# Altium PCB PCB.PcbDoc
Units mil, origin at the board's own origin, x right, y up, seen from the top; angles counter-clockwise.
Board outline 1710 x 3450 mil, 4 copper layers (Top Layer, GND, VCC, Bottom Layer), stack 61.2 mil thick; 25 components, 31 nets, 134 pads, 19 vias.
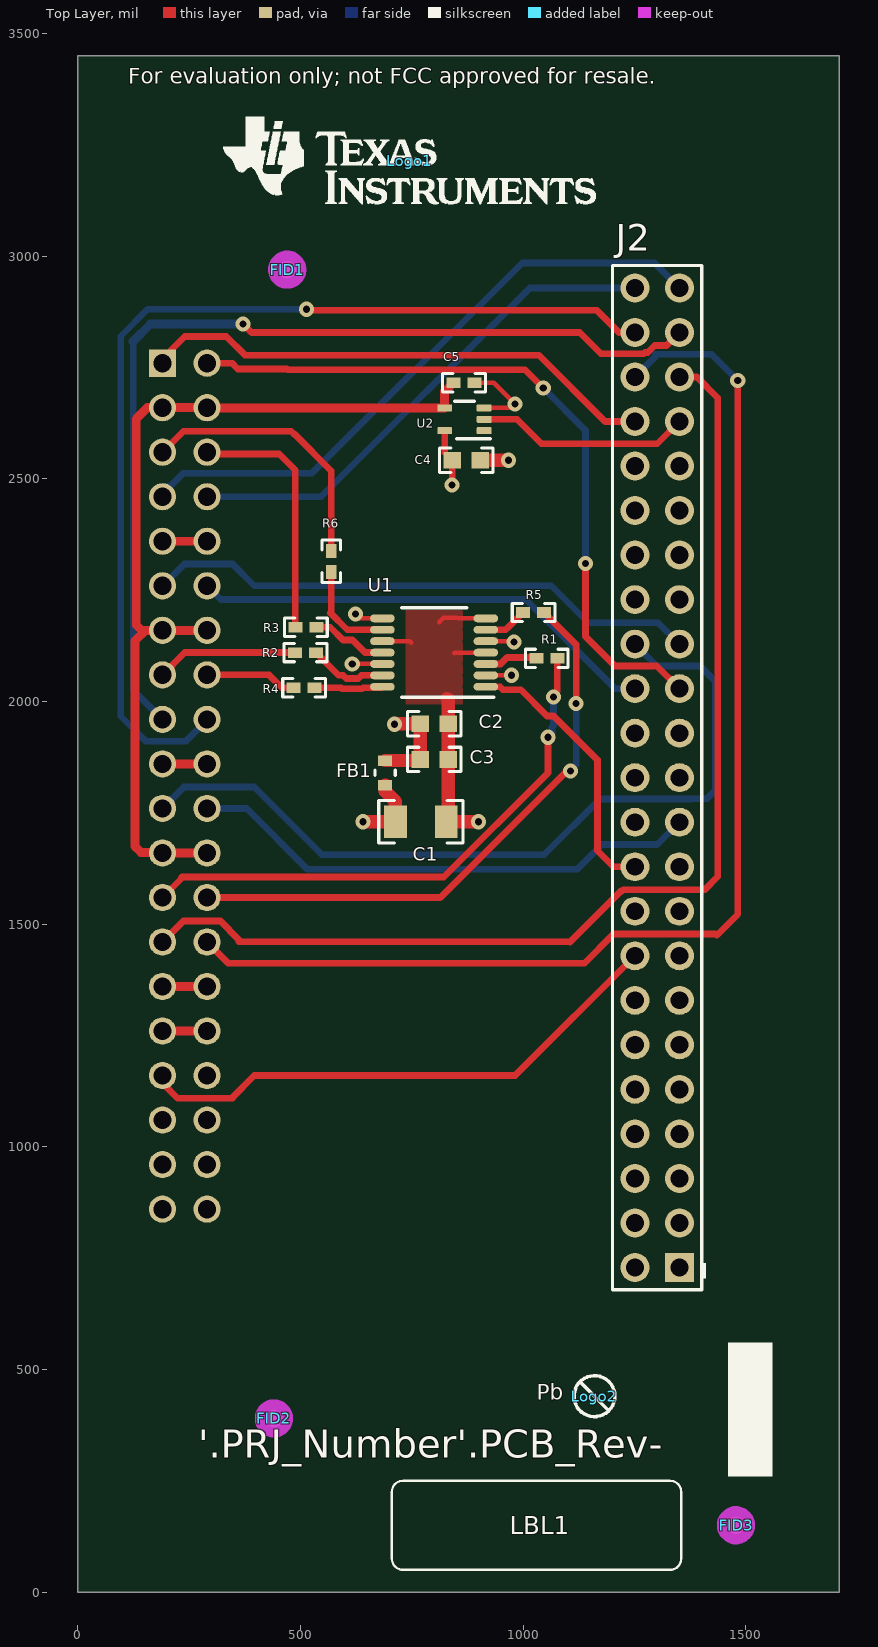
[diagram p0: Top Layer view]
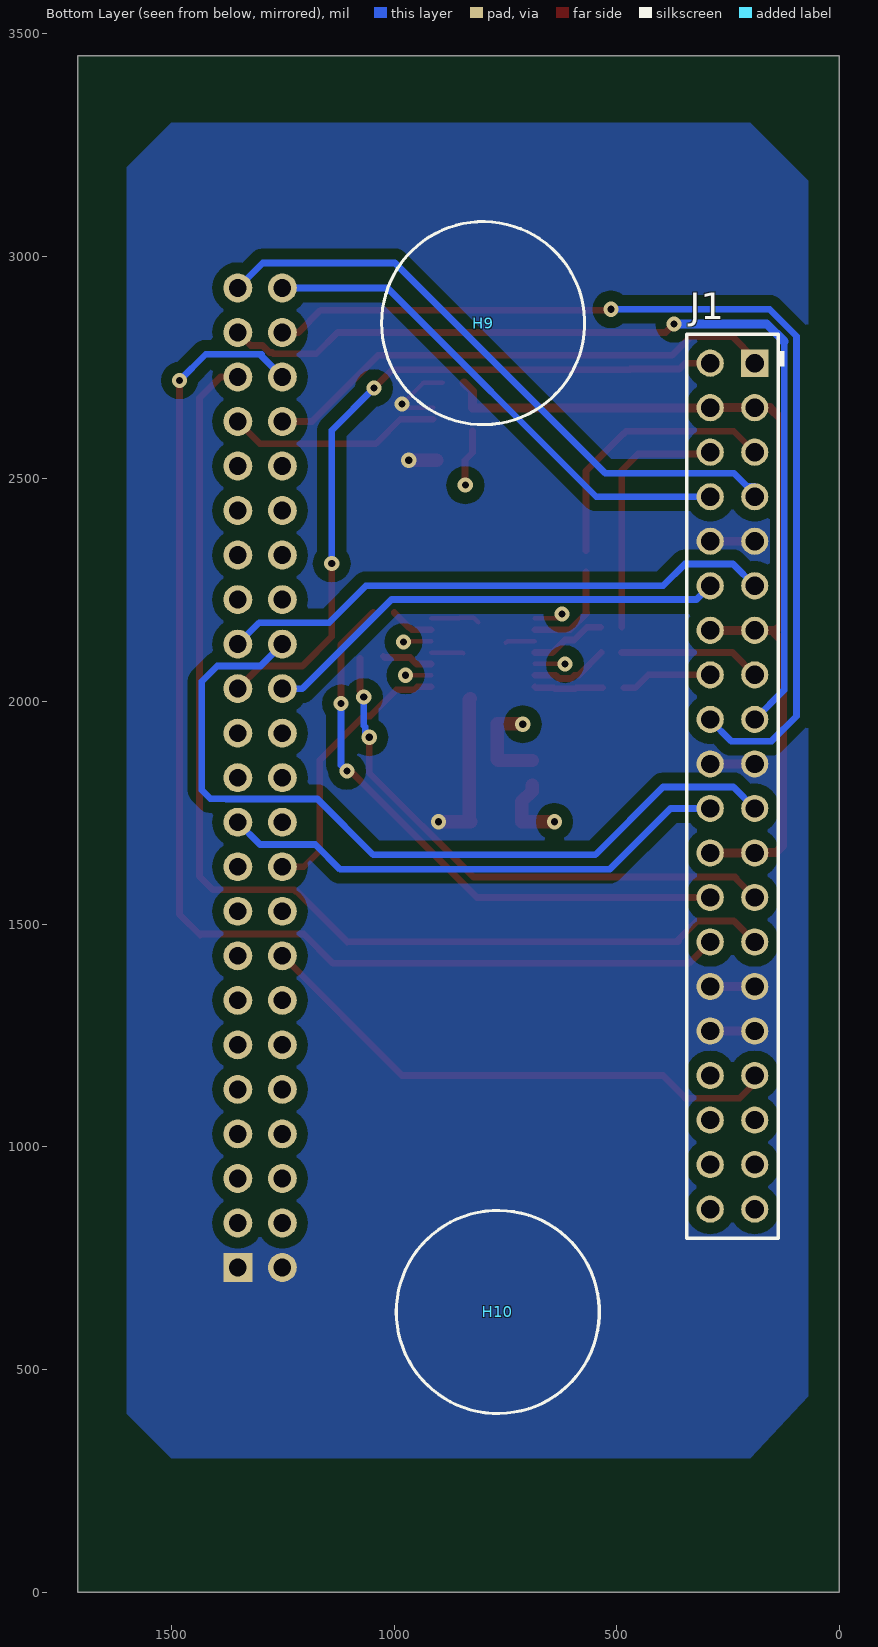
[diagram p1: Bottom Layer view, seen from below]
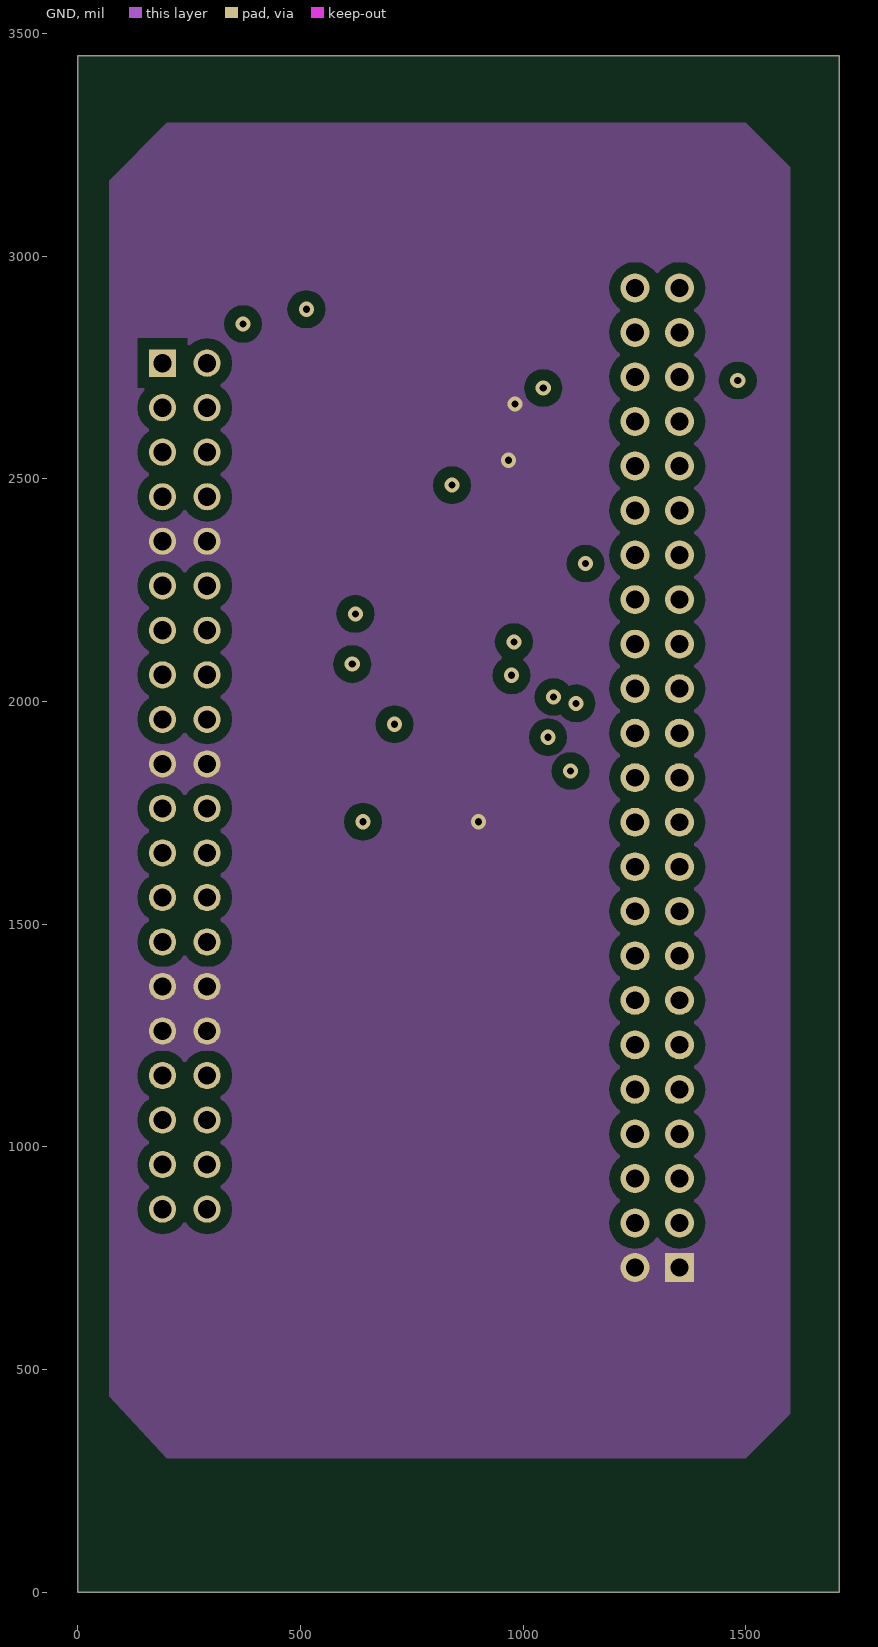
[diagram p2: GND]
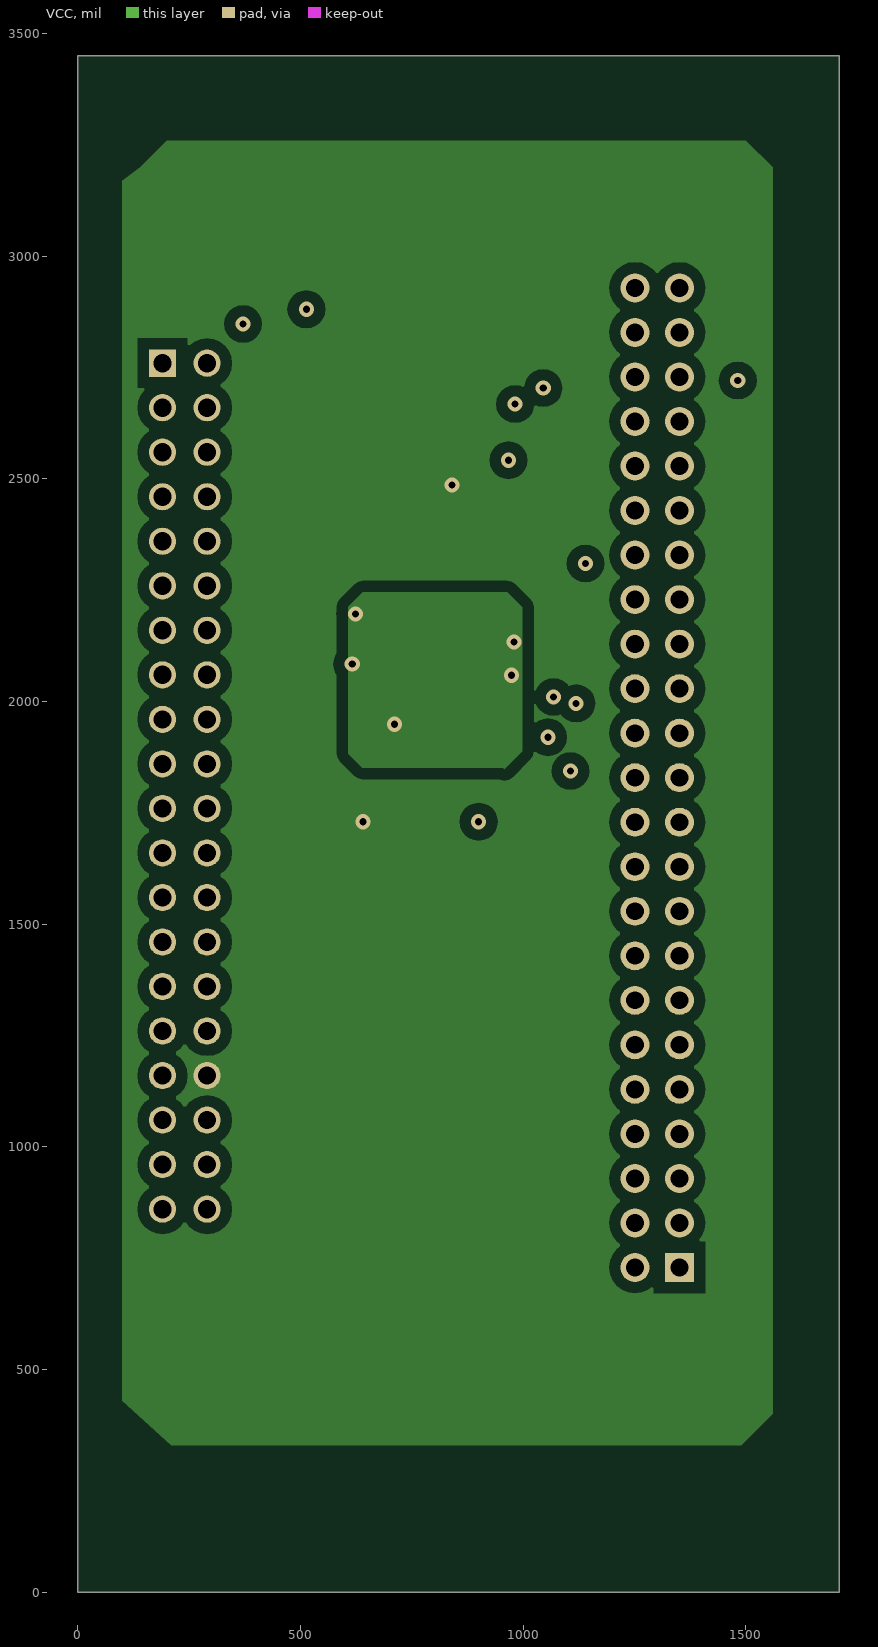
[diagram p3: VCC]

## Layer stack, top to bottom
Top Solder: solder mask 0.4, Solder Resist, Dk 3.5
Top Layer: signal copper 2.8
Dielectric1: core 16.6, FR-4, Dk 4.8
GND: signal copper 2.8
Dielectric 2: dielectric 16.8, FR-4, Dk 4.8
VCC: signal copper 2.8
Dielectric 3: dielectric 16.6, FR-4, Dk 4.8
Bottom Layer: signal copper 2.8
Bottom Solder: solder mask 0.4, Solder Resist, Dk 3.5

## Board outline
0,0 1710,0 1710,3450 0,3450 0,0

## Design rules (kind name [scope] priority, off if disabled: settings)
AcuteAngle [All] p1: minimum=4.50000000000000E+0001 checktracksonly=FALSE
AssemblyTestPointUsage [All] p1: valid=2
BoardOutlineClearance BoardOutlineClearance_MountingHoles [OnCopper and InComponentClass('Mounting Holes')] p1: gap=40
BoardOutlineClearance BoardOutlineClearance_Poly [OnCopper and IsPoly] p2: gap=25
BoardOutlineClearance [OnCopper and Not InComponentClass('Logo') and not InComponentClass('FiducialMark') and not InRegion(1000,500,4000,800) and not InPoly] p3: gap=75
Clearance Clearance_Keepouts [((IsTrack Or IsArc) And Not InPoly) And IsFree and IsKeepOut vs ((IsTrack Or IsArc) And Not InPoly) And IsFree and IsKeepOut] p1: gap=0
Clearance Clearance_Poly [InPolygon] p2: gap=25
Clearance [All] p3: gap=7.87
ComponentClearance ComponentClearance_MountingHoles_FiducialMarks [InComponentClass('Mounting Holes') vs InComponentClass('FiducialMark')] p1: gap=50 collisioncheckmode=3 verticalgap=10 showdistances=FALSE
ComponentClearance ComponentClearance_Shunt [InComponentClass('Header') vs InComponentClass('Shunt')] p2: gap=0 collisioncheckmode=3 verticalgap=0 showdistances=FALSE
ComponentClearance ComponentClearance_Logo [InComponentClass('Logo')] p3: gap=50 collisioncheckmode=3 verticalgap=10 showdistances=FALSE
ComponentClearance ComponentClearance_ScrewToNut [(HasFootprint('NY PMS 440 0025 PH')) vs (HasFootprint('Keystone_1902C'))] p4: gap=5 collisioncheckmode=3 verticalgap=10 showdistances=FALSE
ComponentClearance ComponentClearance_MountingHoles [InComponentClass('Mounting Holes')] p5: gap=250 collisioncheckmode=3 verticalgap=100000 showdistances=FALSE
ComponentClearance ComponentClearance_SmallPassives [HasFootprint('0201*') or HasFootprint('0402*') or HasFootprint('0508') or HasFootprint('0603*') or HasFootprint('0612') or HasFootprint('0805*') or HasFootprint('0815*') or HasFootprint('0830*') or HasFootprint('1206*') or HasFootprint('1210*') or HasFootprint('1808*') or HasFootprint('1812*') or HasFootprint('1825*') or HasFootprint('2010*') or HasFootprint('2220*') or HasFootprint('2225*') or HasFootprint('2512*') or HasFootprint('2728*') or HasFootprint('3518*') vs HasFootprint('0201*') or HasFootprint('0402*') or HasFootprint('0508') or HasFootprint('0603*') or HasFootprint('0612') or HasFootprint('0805*') or HasFootprint('0815*') or HasFootprint('0830*') or HasFootprint('1206*') or HasFootprint('1210*') or HasFootprint('1808*') or HasFootprint('1812*') or HasFootprint('1825*') or HasFootprint('2010*') or HasFootprint('2220*') or HasFootprint('2225*') or HasFootprint('2512*') or HasFootprint('2728*') or HasFootprint('3518*')] p6: gap=14.96 collisioncheckmode=3 verticalgap=10 showdistances=FALSE
ComponentClearance ComponentClearance_THtoSMT [IsThruComponent vs IsSMTComponent] p7: gap=40 collisioncheckmode=3 verticalgap=30 showdistances=FALSE
ComponentClearance ComponentClearance_THtoTH [IsThruComponent vs IsThruComponent] p8: gap=30 collisioncheckmode=3 verticalgap=30 showdistances=FALSE
ComponentClearance [All] p9: gap=30 collisioncheckmode=3 verticalgap=10 showdistances=FALSE
DiffPairsRouting [All] p1: maxlimit=100 minlimit=10 mostfreqgap=10 toplayer_minwidth=15 toplayer_maxwidth=15 toplayer_prefwidth=15 midlayer1_minwidth=15 midlayer1_maxwidth=15 midlayer1_prefwidth=15 midlayer2_minwidth=15 midlayer2_maxwidth=15 midlayer2_prefwidth=15 bottomlayer_minwidth=15 bottomlayer_maxwidth=15 bottomlayer_prefwidth=15 maxuncoupledlength=1000
FabricationTestPointUsage TestPointUsage [All] p1: valid=2 allowmultiple=FALSE
FabricationTestpoint Testpoint [All] p1: side=3 testpointundercomponent=TRUE minsize=40 maxsize=100 preferedsize=60 minholesize=0 maxholesize=40 preferedholesize=32 testpointgrid=1 allowsidetop=TRUE allowsidebottom=TRUE usegrid=TRUE gridtolerance=0.01
FanoutControl Fanout_LCC [IsLCC] p1: bgadir=Out bgaviamode=Centered fanoutstyle=Auto fanoutdirection=Alternating viagrid=1 // Fanout_LCC (Default Rule)
FanoutControl Fanout_BGA [IsBGA] p2: bgadir=Out bgaviamode=Centered fanoutstyle=Auto fanoutdirection=Alternating viagrid=1 // Fanout_BGA (Default Rule)
FanoutControl Fanout_Default [All] p4: bgadir=Out bgaviamode=Centered fanoutstyle=Auto fanoutdirection=Alternating viagrid=1 // Fanout_Default (Default Rule)
FanoutControl Fanout_Small [(CompPinCount < 5)] p5: bgadir=Out bgaviamode=Centered fanoutstyle=Auto fanoutdirection=OutThenIn viagrid=1 // Fanout_Small (Default Rule)
HoleSize [All] p1: absolutevalues=TRUE maxlimit=251 minlimit=7.87 maxpercent=80.000 minpercent=20.000
MinimumAnnularRing MinimumAnnularRing_ThermalPadVias [IsVia and InAnyComponent] p1: minimumring=5.91
MinimumAnnularRing [All] p2: minimumring=8
MinimumSolderMaskSliver MinimumSolderMaskSliver_Logo [InComponentClass('Logo') vs InComponentClass('Logo')] p1: minsoldermaskwidth=0.7
MinimumSolderMaskSliver [All] p2: minsoldermaskwidth=3.94
PlaneConnect [All] p1: planeconnectstyle=Relief reliefexpansion=10 reliefentries=4 reliefconductorwidth=10 reliefairgap=10
PolygonConnect [All] p1: connectstyle=Direct reliefconductorwidth=10 reliefentries=4 polygonreliefangle="90 Angle" airgapwidth=10
RoutingVias ThermalPadVias [IsVia and InAnyComponent] p1: holewidth=7.87 width=19.68 viastyle="Through Hole" minholewidth=7.87 minwidth=19.68 maxholewidth=12.99 maxwidth=23.62
RoutingVias [All] p2: holewidth=16 width=34 viastyle="Through Hole" minholewidth=7.87 minwidth=26 maxholewidth=40 maxwidth=65
SilkToBoardRegionClearance [Not ((IsComment or IsDesignator) And (Hide <> 'False')) and not InRegion(1000,500,4000,800)] p1:
SilkToSilkClearance SilkToSilkClearance_Pb-FreeLogo [(HasFootprint('Pb-Free_Overlay_Medium') OR HasFootprint('Pb-Free_Overlay_Small')) vs (HasFootprint('Pb-Free_Overlay_Medium') OR HasFootprint('Pb-Free_Overlay_Small'))] p1: silktosilkclearance=0
SilkToSilkClearance [All] p2: silktosilkclearance=4
SilkToSolderMaskClearance SilkToComponentPadClearance [(IsPad or IsFill or IsRegion) and InAnycomponent] p1: minsilkscreentomaskgap=5 clearancetoexposedcopper=TRUE
SilkToSolderMaskClearance "Silk to Solder Mask Opening" [All] p2: minsilkscreentomaskgap=4 clearancetoexposedcopper=FALSE
SolderMaskExpansion [All] p1: expansion=1.97
Width [All] p1: maxlimit=100 minlimit=6 preferedwidth=10 checkconnectedcopper=TRUE
15 further rules are at their usual default settings.

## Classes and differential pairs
component class Sheet1: C1 C2 C3 C4 C5 FB1 J1 R1 R2 R3 R4 R5 R6 U1 U2
component class Logo: Logo1
component class EVM_Hardware: FID1 FID2 FID3 H9 H10 LBL1 Logo1 Logo2 Logo3
component class FiducialMark: FID1 FID2 FID3
component class Label: LBL1

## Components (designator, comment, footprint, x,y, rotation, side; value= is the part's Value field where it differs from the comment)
C1 "885012208069" 1206 770,1730 r0 top
C2 "06033C104JAT2A" 0603 800,1950 r0 top
C3 "CGA3E3X5R1H105K080AB" 0603 800,1870 r0 top
C4 "GRM188R71C104KA01D" 0603 872,2542 r0 top
C5 "GRM1555C1E470JA01D" 0402 867,2716 r0 top
FB1 "MMZ1608B102CTA00" MMZ1608_095 690,1840 r270 top
FID1 "Fiducial" Fiducial10-20 470,2970 r0 top
FID2 "Fiducial" Fiducial10-20 440,390 r0 top
FID3 "Fiducial" Fiducial10-20 1478,150 r0 top
H9 "SJ-5303 (CLEAR)" Bumpon_SJ5003Transparent 800,2850 r180 bottom
H10 "SJ-5303 (CLEAR)" Bumpon_SJ5003Transparent 767,629 r180 bottom
J1 "SSW-120-01-T-D" Samtec_SSW-120-01-x-D 239.99,1810 r270 bottom
J2 "PBC23DFAN" Sullins_PBC23DFAN 1301,1829 r180 top
LBL1 "Size: 0.65\" x 0.20 \"" Label_650x200 1030,150 r0 top
Logo1 "Texas Instruments" TI_Stacked_Overlay_Small 745,3215 r0 top
Logo2 "Pb-Free Symbol" Pb-Free_Overlay_Small 1160,440 r0 top
Logo3 "FCC disclaimer" FCC_disclaimer 2350,3380 r0 top
R1 "CRCW04020000Z0ED" 0402 1053,2097 r180 top
R2 "CRCW04020000Z0ED" 0402 508,2031 r0 top
R3 "CRCW04020000Z0ED" 0402 512,2167 r0 top
R4 "CRCW04020000Z0ED" 0402 511,2110 r0 top
R5 "CRCW04020000Z0ED" 0402 1023.49,2200.01 r180 top
R6 "CRCW04020000Z0ED" 0402 569,2315 r270 top
U1 "CDCLVC1106PWR" PW0014A_N 800,2110 r180 top
U2 "SN74LVC1G17DCKR" DCK0005A_N 868,2634 r180 top

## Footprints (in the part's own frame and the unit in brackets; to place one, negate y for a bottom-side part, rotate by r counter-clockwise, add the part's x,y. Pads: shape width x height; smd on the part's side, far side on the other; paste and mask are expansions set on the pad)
0402 [mm] "0402 from SM-752 data"
  rect 0.8x0.6 smd: 1(-0.6,0) 2(0.6,0)
  silkscreen extent -1.22,-0.52 1.22,0.52, body extent -0.55,-0.3 0.55,0.3, height 0.6
0603 [mm] "0603 from SM-752 data"
  rect 1x0.95 smd: 1(-0.8,0) 2(0.8,0)
  silkscreen extent -1.52,-0.69 1.52,0.69, body extent -0.87,-0.47 0.87,0.47, height 1
1206 [mm] "1206 from SM-752 data"
  rect 1.3x1.85 smd: 1(-1.45,0) 2(1.45,0)
  silkscreen extent -2.4,-1.21 2.4,1.21, body extent -1.7,-0.9 1.7,0.9, height 1.35
Bumpon_SJ5003Transparent [mil] "3M Hemispherical Bumpon transparent"
  round 1 on Mech4: 0(0,0)
  silkscreen extent -228,-228 228,228, body extent -219,-219 219,219, height 197
DCK0005A_N [mm] "SOT353, 5-Leads, Body 2x1.3mm, Pitch 0.65mm, Lead Span 2.1mm, IPC Medium Density"
  rrect25% 0.85x0.4 smd: 1(-1.125,0.65) 2(-1.125,0) 3(-1.125,-0.65) 4(1.125,-0.65) 5(1.125,0.65)
  silkscreen extent -1.48,-1.02 0.55,1.1, body extent -1.14,-1 1.14,1, height 0.95
FCC_disclaimer [mil]
Fiducial10-20 [mm]
  round 1 smd mask+0.5: 1(0,0)
  Top Layer keep-out circle w1.178: c0,0 r0.5
Label_650x200 [mil] "Thermal Transfer Label"
  silkscreen extent -325,-100 325,100, body extent -325,-100 325,100, height 1
MMZ1608_095 [mm] "TDK"
  rect 0.6x0.8 smd: 1(-0.7,0) 2(0.7,0)
  silkscreen extent -0.15,-0.58 0.15,0.58, body extent -0.87,-0.47 0.87,0.47, height 0.95
Pb-Free_Overlay_Small [mil]
  silkscreen extent -46,-46 46,46
PW0014A_N [mm] "TSOP, 14-Leads, Body 5x4.4mm, Pitch 0.65mm, IPC Medium Density"
  oval 1.4x0.45 smd: 1(-2.95,1.95) 2(-2.95,1.3) 3(-2.95,0.65) 4(-2.95,0) 5(-2.95,-0.65) 6(-2.95,-1.3) 7(-2.95,-1.95) 8(2.95,-1.95) 9(2.95,-1.3) 10(2.95,-0.65) 11(2.95,0) 12(2.95,0.65) 13(2.95,1.3) 14(2.95,1.95)
  silkscreen extent -3.4,-2.55 1.85,2.55, body extent -3.21,-2.5 3.21,2.5, height 1
Samtec_SSW-120-01-x-D [mm] "Receptacle, 2.54mm, 2x20, TH"
  rect 1.55x1.55 hole 1.04: 1(-24.13,1.27)
  round 1.55 hole 1.04: 2(-24.13,-1.27) 3(-21.59,1.27) 4(-21.59,-1.27) 5(-19.05,1.27) 6(-19.05,-1.27) 7(-16.51,1.27) 8(-16.51,-1.27) 9(-13.97,1.27) 10(-13.97,-1.27) 11(-11.43,1.27) 12(-11.43,-1.27) 13(-8.89,1.27) 14(-8.89,-1.27) 15(-6.35,1.27) 16(-6.35,-1.27) 17(-3.81,1.27) 18(-3.81,-1.27) 19(-1.27,1.27) 20(-1.27,-1.27) 21(1.27,1.27) 22(1.27,-1.27) 23(3.81,1.27) 24(3.81,-1.27) 25(6.35,1.27) 26(6.35,-1.27) 27(8.89,1.27) 28(8.89,-1.27) 29(11.43,1.27) 30(11.43,-1.27) 31(13.97,1.27) 32(13.97,-1.27) 33(16.51,1.27) 34(16.51,-1.27) 35(19.05,1.27) 36(19.05,-1.27) 37(21.59,1.27) 38(21.59,-1.27) 39(24.13,1.27) 40(24.13,-1.27)
  silkscreen extent -25.78,-2.6 25.78,2.97, body extent -25.65,-2.48 25.65,2.48, height 8.41
Sullins_PBC23DFAN [mm] "Header, 100mil, 23x2, TH"
  rect 1.65x1.65 hole 1.016: 1(-1.27,27.94)
  round 1.65 hole 1.016: 2(1.27,27.94) 3(-1.27,25.4) 4(1.27,25.4) 5(-1.27,22.86) 6(1.27,22.86) 7(-1.27,20.32) 8(1.27,20.32) 9(-1.27,17.78) 10(1.27,17.78) 11(-1.27,15.24) 12(1.27,15.24) 13(-1.27,12.7) 14(1.27,12.7) 15(-1.27,10.16) 16(1.27,10.16) 17(-1.27,7.62) 18(1.27,7.62) 19(-1.27,5.08) 20(1.27,5.08) 21(-1.27,2.54) 22(1.27,2.54) 23(-1.27,0) 24(1.27,0) 25(-1.27,-2.54) 26(1.27,-2.54) 27(-1.27,-5.08) 28(1.27,-5.08) 29(-1.27,-7.62) 30(1.27,-7.62) 31(-1.27,-10.16) 32(1.27,-10.16) 33(-1.27,-12.7) 34(1.27,-12.7) 35(-1.27,-15.24) 36(1.27,-15.24) 37(-1.27,-17.78) 38(1.27,-17.78) 39(-1.27,-20.32) 40(1.27,-20.32) 41(-1.27,-22.86) 42(1.27,-22.86) 43(-1.27,-25.4) 44(1.27,-25.4) 45(-1.27,-27.94) 46(1.27,-27.94)
  silkscreen extent -2.79,-29.21 2.54,29.21, body extent -2.54,-29.21 2.54,29.21, height 10.62
TI_Stacked_Overlay_Small [mil]
  silkscreen extent -418,-98 418,98

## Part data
C1: library part GRM31CR71E106KA12L, "CAP, CERM, 10uF, 25V, +/-10%, X7R, 1206"
C2: "CAP, CERM, 0.1uF, 25V, +/-5%, X7R, 0603"
C3: library part GRM188R61H105KAALD, "CAP, CERM, 1uF, 50V, +/-10%, X5R, 0603"
C4: "CAP, CERM, 0.1 µF, 16 V, +/- 10%, X7R, 0603"
C5: "CAP, CERM, 47 pF, 25 V,+/- 5%, C0G/NP0, 0402"
FB1: "Ferrite Bead, 1000 ohm @ 100 MHz, 0.3 A, 0603"
FID1 FID2 FID3: "Fiducial mark.  There is nothing to buy or mount."
H9 H10: "Bumpon, Hemisphere, 0.44 X 0.20, Clear"
J1: "Receptacle, 2.54mm, 2x20, TH"
J2: "Header, 100 mil, 23x2, Gold, TH"
LBL1: library part THT-14-423-10, "Thermal Transfer Printable Labels, 0.650\" W x 0.200\" H - 10,000 per roll"
Logo1: library part TI_Logo, "Texas Instrument Corporate Signature"
Logo2: library part Pb-Free
Logo3: library part FCC_disclaimer, "FCC_disclaimer"
R1 R2 R3 R4 R5 R6: "RES, 0, 5%, 0.063 W, 0402"
U1: "Low Jitter, 1:6 LVCMOS Fan-out Clock Buffer, PW0014A (TSSOP-14)"
U2: "SINGLE SCHMITT-TRIGGER BUFFER, DCK0005A (SOT-SC70-5)"

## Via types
v1: diameter 34, hole 16, Top Layer to Bottom Layer, 19 vias

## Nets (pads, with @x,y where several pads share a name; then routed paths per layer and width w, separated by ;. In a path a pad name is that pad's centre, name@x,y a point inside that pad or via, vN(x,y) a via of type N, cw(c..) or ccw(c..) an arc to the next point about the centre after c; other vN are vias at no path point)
+3.3V: C1.1 C4.1 FB1.2 J1.34 U2.5 | length 294.4
  Top Layer w15: U2.5 823.71,2558.8 C4.1 840.5,2490.5 840,2490 v1(840,2486)
  Top Layer w30: v1(640,1730) C1.1 712.91,1775.67 690,1798.58 FB1.2
CS1: C5.1 J1.3 J1.4 J1.13 J1.14 J1.23 J1.24 U2.4 | length 2054.7
  Top Layer w20: J1.24 J1.23 189,1661 142,1661 128,1675 128,2136 145,2153 145,2158 ; J1.14 J1.13 147,2160 145,2158 ; C5.1 823.71,2696.33 U2.4 290.41,2659.59 J1.4 J1.3 156,2660 131,2635 131,2172 145,2158
CS1TO6: J2.39 U2.2 | length 482.2
  Top Layer w15: U2.2 986,2634 1041,2579 1301,2579 J2.39
DGND: C1.2 C2.2 C3.2 C4.2 C5.2 J1.9 J1.10 J1.19 J1.20 J1.29 J1.30 J1.31 J1.32 J2.1 J2.2 U1.4 U1.7 U1.10 U2.3 | length 1248.7
  Top Layer w10: U1.10 745.41,2135.59 749,2132 ; 811,2178 821,2188 852,2188 853.23,2186.77 U1.7 ; 845,2109 846,2110 U1.4 ; C5.2 934,2716 v1(982,2668) 973.59,2659.59 U2.3
  Top Layer w20: J1.31 J1.32 ; J1.29 J1.30 ; J1.19 J1.20 ; J1.9 J1.10
  Top Layer w30: 829,2007 831.5,2004.5 C2.2 C3.2 831.5,1734.41 C1.2 v1(900,1730) ; C4.2 v1(967,2542)
NetC2_1: C2.1 C3.1 FB1.1 U1.2 U1.5 U1.8 U1.12 | length 473.8
  Top Layer w10: v1(616,2084) 616.41,2084.41 U1.12 ; v1(623,2197) 623,2191.54 627.77,2186.77 U1.8 ; U1.2 967.82,2058.82 968,2059 v1(974,2059) ; U1.5 977.41,2135.59 v1(979,2134)
  Top Layer w30: FB1.1 766.06,1867.56 C3.1 C2.1 v1@712,1950
  other v1: 711,1949
NetR1_2: R1.2 U1.3 | length 115.1
  Top Layer w15: U1.3 949.41,2084.41 964,2099 1021.1,2099 R1.2@1024.02,2101.93
NetR2_2: R2.2 U1.14 | length 155
  Top Layer w15: R2.2 590.87,2031 593.12,2028.75 638.88,2028.75 641.13,2031 681.63,2031 U1.14
NetR3_2: R3.2 U1.11 | length 171.8
  Top Layer w15: R3.2 566.65,2167 595.34,2138.31 616.24,2138.31 644.55,2110 U1.11
NetR4_2: R4.2 U1.13 | length 176.4
  Top Layer w15: R4.2 585.8,2058.82 595.4,2058.82 602.59,2051.63 629.41,2051.63 636.6,2058.82 U1.13
NetR5_2: R5.2 U1.6 | length 99.8
  Top Layer w15: U1.6 960.4,2161.18 965.59,2166.37 966.23,2166.37 R5.2
NetR6_2: R6.2 U1.9 | length 225.7
  Top Layer w15: R6.2 569,2201 567,2199 604.82,2161.18 U1.9
OE: J1.33 J2.16 | length 1225.8
  Top Layer w15: J1.33 189.99,1143.01 224,1109 347,1109 347,1111 396,1160 982,1160 J2.16
SCLK_1: J1.5 R6.1 | length 614.7
  Top Layer w15: J1.5 237,2607 479,2607 485,2601 486,2601 569,2518 R6.1
SCLK_2: J1.6 R3.1 | length 567.7
  Top Layer w15: J1.6 294,2556 452,2556 488.38,2519.62 R3.1
SCLK_3: J1.15 R4.1 | length 320.1
  Top Layer w15: J1.15 240,2110 R4.1@489.37,2110
SCLK_4: J1.16 R2.1 | length 206.4
  Top Layer w15: J1.16 429,2060 458,2031 R2.1
SCLK_5: J1.25 R1.1 | length 1243.6
  Top Layer w15: J1.25 232,1602 232,1604 233.89,1605.89 821.67,1605.89 1055.69,1839.9 v1(1055.69,1919.82) ; v1@1068,2015 1076.62,2023.62 R1.1
  Bottom Layer w15: v1(1055.69,1919.82) 1064.81,1928.94 1064.81,1943.08 1068,1946.26 v1(1068,2010)
SCLK_6: J1.26 R5.1 | length 1331.3
  Top Layer w15: J1.26 814,1560 1098,1844 v1(1106,1844) ; R5.1 1119,2128.12 v1(1119,1996)
  Bottom Layer w15: v1@1099.51,1844 v1(1106,1844) 1119,1857 v1(1119,1996)
SCLK_16: J2.20 U1.1 | length 621.9
  Top Layer w15: U1.1 947.99,2033.23 954.59,2026.63 994.66,2026.63 1053.65,1967.64 1068,1967.64 1166.64,1869 1167,1869 1167,1664.78 1202.78,1629 J2.20
SDI_1: J1.1 J2.40 | length 1170.8
  Top Layer w15: J1.1 189.99,2770 239.99,2820 333,2820 375,2778 1035,2778 1184,2629 J2.40
SDI_2: J1.2 J2.27 | length 1635
  Top Layer w15: J1.2 346,2760 359,2747 469.51,2747 471,2745.51 1003.49,2745.51 v1(1045,2704) ; v1(1140,2310) 1140,2146 1206,2080 1300,2080 J2.27
  Bottom Layer w15: v1(1045,2704) 1140,2609 v1(1140,2310)
SDI_3: J1.11 J2.29 | length 1255.9
  Bottom Layer w15: J1.11 238.99,2309 347,2309 396,2260 1063,2260 1146,2177 1303,2177 J2.29
SDI_4: J1.12 J2.28 | length 1056.7
  Bottom Layer w15: J1.12 320.61,2229.37 1005.63,2229.37 1206,2029 J2.28
SDI_5: J1.21 J2.30 | length 1844.7
  Bottom Layer w15: J1.21 237.99,1808 396,1808 548,1656 1047,1656 1172.15,1781.15 1376.82,1781.15 1377.68,1782 1413,1782 1432,1801 1432,2045 1397,2080 1300,2080 J2.30
SDI_6: J1.22 J2.21 | length 1161.5
  Bottom Layer w15: J1.22 379,1760 515.78,1623.22 1121.22,1623.22 1177,1679 1301,1679 J2.21
SDO_1: J1.7 J2.45 | length 1394
  Bottom Layer w15: J1.7@190,2482.87 202.47,2482.87 204.67,2480.67 237,2513 526,2513 998,2985 1295,2985 J2.45
SDO_2: J1.8 J2.46 | length 1155.3
  Bottom Layer w15: J1.8 546,2460 1015,2929 J2.46
SDO_3: J1.17 J2.43 | length 2167
  Top Layer w15: v1(371,2848) 390,2829 1127,2829 1174.85,2781.15 1270.82,2781.15 1273.68,2784 1279.65,2784 1295.53,2799.87 1321.87,2799.87 J2.43
  Bottom Layer w15: 124,2809 124,2025.99 J1.17
  Bottom Layer w20: 124,2809 163,2848 v1(371,2848)
SDO_4: J1.18 J2.44 | length 2293.6
  Top Layer w15: v1(513,2881) 515,2879 1165,2879 1215,2829 J2.44
  Bottom Layer w15: J1.18 289.99,1957.99 243,1911 152,1911 96.13,1966.87 96.13,2820.55 156.58,2881 v1(513,2881)
SDO_5: J1.27 J2.41 | length 2529.8
  Top Layer w15: J1.27 236.95,1506.96 319.97,1506.96 361,1465.93 361,1461 1105,1460 1219.49,1574.49 1221.86,1574.49 1224.37,1577 1407,1577 1437,1607 1437,2682 1390,2729 J2.41
SDO_6: J1.28 J2.42 | length 2738.4
  Top Layer w15: J1.28 337.98,1412 1137,1412 1203,1478 1432,1478 1435,1475 1482,1522 v1(1482,2721)
  Bottom Layer w15: J2.42 1297,2775 1297,2780 1423,2780 v1(1482,2721)
pads on no net: FID1.1 FID2.1 FID3.1 H9.0 H10.0 J1.35 J1.36 J1.37 J1.38 J1.39 J1.40 J2.3 J2.4 J2.5 J2.6 J2.7 J2.8 J2.9 J2.10 J2.11 J2.12 J2.13 J2.14 J2.15 J2.17 J2.18 J2.19 J2.22 J2.23 J2.24 J2.25 J2.26 J2.31 J2.32 J2.33 J2.34 J2.35 J2.36 J2.37 J2.38 U2.1

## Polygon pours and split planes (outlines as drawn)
DGND on GND "GND_DGND_P001" (solid, pour order 1): 70,3170 200,3300 1500,3300 1600,3200 1600,400 1500,300 200,300 70,440
+3.3V on VCC "VCC-No Net" (solid, pour order 2): 100,560 100,1860 100,2545.51 100,3170 140,3200 200,3260 1500,3260 1560,3200 1560,400 1490,330 210,330 100,430 100,470 100,500
NetC2_1 on VCC "Top Layer-No Net" (solid, pour order 0): 607,2213 640,2246 964,2246 997,2213 998,2212 998,1889 998,1888 958,1848 955,1851 641,1851 639,1851 607,1883 607,2213
DGND on Bottom Layer "BOTTOM_LAYER_DGND_P003" (solid, pour order 3): 70,3170 200,3300 1500,3300 1600,3200 1600,400 1500,300 200,300 70,440
DGND on Top Layer "Top Layer-No Net 1" (solid, pour order 7): 736,2205 864,2206.46 864,2193.51 864,1994 736,1994

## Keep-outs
Keep-Out Layer:
  text ".Layer_Name" at 577,-858.49 h60

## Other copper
Top Layer:
  text ".Layer_Name" at 577,-858.49 h60
Bottom Layer:
  text ".Layer_Name" at 577,-858.49 h60

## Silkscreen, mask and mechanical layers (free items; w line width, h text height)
Top Overlay:
  region: 1560,260 1560,560 1460,560 1460,260
  text "'.PRJ_Number'.PCB_Rev-" at 270,280 h108.27
  text ".Layer_Name" at 577,-858.49 h60
Bottom Overlay:
  text ".Layer_Name" at 577,-858.49 h60
Top Paste:
  text ".Layer_Name" at 577,-858.49 h60
Bottom Paste:
  text ".Layer_Name" at 577,-858.49 h60
Top Solder:
  text ".Layer_Name" at 577,-858.49 h60
  text ".Layer_Name" at 577,-858.49 h60
Bottom Solder:
  text ".Layer_Name" at 577,-858.49 h60
Drill Guide:
  text ".Layer_Name" at 577,-858.49 h60
M1 Board Outline:
  the board outline again, w10
  text ".Layer_Name" at 577,-858.49 h60
M2 Board Dimensions:
  rectangle: 0,-275 125,-150
  rectangle: 125,-400 500,-275
  lines w7: 0,-275 1000,-275 ; 125,-400 125,-150 ; 250,-400 250,-150 ; 500,-400 500,-150 ; 750,-400 750,-150 ; 0,-400 1000,-400 1000,-150 0,-150 0,-400
  text ".Layer_Name" at 577,-858.49 h60
M3 3D STEP Top:
  text ".Layer_Name" at 577,-858.49 h60
M4 3D STEP Bottom:
  text ".Layer_Name" at 577,-858.49 h60
M5 Assembly Top:
  lines w10: -292,-930.17 6308,-930.17 ; -292,-726.83 6310,-726.83 ; -292,-523.5 -292,-1133.5 3713,-1133.5 6310,-1133.5 6310,-523.5 -291.5,-523.5 -291.5,-1133.5 1284,-1133.5 ; 2173,-1133.5 2173,-523.5 ; 3440,-726.83 3440,-523.5 ; 4280,-726.83 4280,-523.5 ; 4902,-1140 4902,-937.17
  text "COMPONENTS MARKED 'DNP' SHOULD NOT BE POPULATED." at 1153.5,-318.5 h60
  text "ASSEMBLY VARIANT:" at 1153,-434 h60
  text ".VariantName" at 2189,-434 h60
  text "PCB VIEWED FROM TOP SIDE" at -228.5,-655.67 h60
  text "BOARD #:" at 2248,-655.67 h60
  text ".PRJ_Number" at 2793.5,-655.67 h60
  text "REV:" at 3638,-655.67 h60
  text ".PCB_Rev" at 3929.5,-655.67 h60
  text "SVN REV:" at 4476,-655.67 h60
  text ".VersionControl_RevNumber" at 4982,-655.67 h60
  text "TID #:" at 2248,-859 h60
  text ".TID" at 2793.5,-859 h60
  text "PLOT NAME =" at -228.5,-1064.34 h60
  text ".plot_File_Name" at 577,-1064.34 h60
  text "GENERATED    :" at 2250,-1064.34 h60
  text ".Print_Date" at 3119.5,-1064.34 h60
  text ".Print_Time" at 3848.5,-1064.34 h60
  text "TEXAS INSTRUMENTS" at 5113,-1064.34 h60
M6 Assembly Bottom:
  lines w10: -292.5,-727.33 6309.5,-727.33 ; -290.5,-930.67 6309.5,-930.67 ; 1115.5,-1140.5 1115.5,-937.67 ; 1737.5,-727.33 1737.5,-524 ; 2577.5,-727.33 2577.5,-524 ; 3844.5,-1134 3844.5,-524 ; 4733.5,-1134 6309,-1134 6309,-524 -292.5,-524 -292.5,-1134 2304.5,-1134 6309.5,-1134 6309.5,-524
  text "COMPONENTS MARKED 'DNP' SHOULD NOT BE POPULATED." at 6102,-318 h60
  text ".VariantName" at 5058,-434 h60
  text "ASSEMBLY VARIANT:" at 6097,-434 h60
  text ".VersionControl_RevNumber" at 1035.5,-656.17 h60
  text "SVN REV:" at 1541.5,-656.17 h60
  text ".PCB_Rev" at 2088,-656.17 h60
  text "REV:" at 2379.5,-656.17 h60
  text ".PRJ_Number" at 3224,-656.17 h60
  text "BOARD #:" at 3769.5,-656.17 h60
  text "PCB VIEWED FROM BOTTOM SIDE" at 6246,-656.17 h60
  text ".TID" at 3224,-859.5 h60
  text "TID #:" at 3769.5,-859.5 h60
  text "TEXAS INSTRUMENTS" at 904.5,-1064.84 h60
  text ".Print_Time" at 2169,-1064.84 h60
  text ".Print_Date" at 2898,-1064.84 h60
  text "GENERATED    :" at 3767.5,-1064.84 h60
  text ".plot_File_Name" at 5440.5,-1064.84 h60
  text "PLOT NAME =" at 6246,-1064.84 h60
M9 Title Sheet:
  drawing of 57 lines, arcs and shapes, not listed
  text "1" at 739.84,8036.5 h70
  text "2" at 3235.5,8036.5 h70
  text "3" at 5724.84,8036.5 h70
  text "4" at 8231.51,8036.5 h70
  text "5" at 10730.5,8036.5 h70
  text "6" at 13235.5,8036.5 h70
  text "A" at -416.5,6893.5 h70
  text "A" at 14383.5,6893.5 h70
  text "B" at -416.5,4513.5 h70
  text "B" at 14383.5,4513.5 h70
  text "C" at -416.5,2138.5 h70
  text "C" at 14383.5,2138.5 h70
  text "PROJECT TITLE:" at 11343.5,277.5 h45
  text ".PRJ_Title" at 11393.5,144.17 h70
  text "DESIGNED FOR:" at 11343.5,-23.5 h45
  text ".PRJ_Customer" at 11393.5,-163.5 h70
  text "D" at -416.5,-231.5 h70
  text "D" at 14383.5,-231.5 h70
  text "FILE NAME:" at 11343.5,-323.5 h45
  text ".PCB_File_Name_No_Path" at 11393.5,-443.5 h70
  text "Texas Instruments (TI) and/or its licensors do not warrant the accuracy or completeness of this specification" at 6374,-605.34 h45
  text "ENGINEER:" at 11343.5,-613.5 h45
  text "LAYOUT BY:" at 12848.5,-613.5 h45
  text "or any information contained therein. TI and/or its licensors do not warrant that this design will meet" at 6329.01,-718 h45
  text ".PRJ_Engineer" at 11393.5,-768.49 h70
  text ".PCB_Layout" at 12899,-768.49 h70
  text "the specifications, will be suitable for your application or fit for any particular purpose, or will operate in" at 6329.01,-830.67 h45
  text ".Layer_Name" at 577,-858.49 h60
  text "ALTIUM DESIGNER VERSION:" at 12848.5,-923.5 h45
  text "an implementation. TI and/or its licensors do not warrant that the design is production worthy. You should" at 6329.01,-943.33 h45
  text "completely validate and test your design implementation to confirm the system functionality for your application." at 6374,-1056 h45
  text ".print_Scale" at 11393.5,-1056.83 h70
  text ".Application_BuildNumber" at 12899,-1056.83 h70
  text "1" at 739.84,-1263.5 h70
  text "2" at 3235.5,-1263.5 h70
  text "3" at 5724.84,-1263.5 h70
  text "4" at 8231.51,-1263.5 h70
  text "5" at 10730.5,-1263.5 h70
  text "6" at 13235.5,-1263.5 h70
M10 Fab Notes:
  drawing of 173 lines, arcs and shapes, not listed
  text "DESIGN INFORMATION" at 12378.02,6201 h60
  text "MIN. TRACK WIDTH:" at 11733.46,6021 h60
  text "8" at 12829.7,6021 h60
  text "MIL" at 12984.46,6021 h60
  text "MIN. CLEARANCE:" at 11733.46,5889 h60
  text "0.2" at 12769.7,5889 h60
  text "mm" at 12984.46,5889 h60
  text "MIN. VIA PAD SIZE:" at 11733.46,5757 h60
  text "24" at 12799.71,5757 h60
  text "MIL" at 12984.46,5757 h60
  text "0.05mm (2MIL)" at 12428.46,5615.29 h60
  text "MINIMUM ANNULAR RING" at 11404.23,5611 h60
  text "EXTERNAL" at 13136.46,5611 h60
  text "PER" at 11604.23,5493 h60
  text "IPC-D-275 CLASS 2 LEVEL C" at 11824.23,5493 h60
  text "MIL, HOLES" at 13312.46,5380.71 h60
  text "+/-" at 12920,5380 h60
  text "+/-" at 13774,5380 h60
  text "REGISTRATION TOLERANCES:" at 11404.23,5375 h60
  text "METAL" at 12604,5375 h60
  text "5" at 13180.2,5375 h60
  text "3" at 14013.2,5375 h60
  text "MIL" at 14129.46,5375 h60
  text "+/-" at 13774,5262 h60
  text "HOLE SIZE TOLERANCE (UNLESS OTHERWISE SPECIFIED):" at 11404.23,5257 h60
  text "3" at 14013.2,5257 h60
  text "MIL" at 14129.46,5257 h60
  text "MATERIAL:" at 11329.46,5047.54 h60
  text "FR-4 High Tg" at 12315.9,4907.21 h60
  text "FR-408" at 11750.46,4898.64 h60
  text "OTHER" at 13238.46,4898.64 h60
  text "X" at 12161,4895 h60
  text "62 MIL (1.6mm) +/-10%" at 12070.56,4735.92 h60
  text "THICKNESS:" at 11404.23,4731.64 h60
  text "X" at 11942.4,4731.64 h60
  text "OTHER" at 13355.46,4731.64 h60
  text "TOLERANCE:" at 11404.23,4573.64 h60
  text "X" at 12243.53,4573.64 h60
  text "ANSI IPC-6012 TYPE 3 CLASS 2" at 12430.48,4573.64 h60
  text "OTHER +/-" at 12430.46,4417.64 h60
  text "BOW & TWIST:" at 11404.23,4260.64 h60
  text "X" at 12243.53,4260.64 h60
  text "ANSI IPC-6012 TYPE 3 CLASS 2" at 12430.48,4260.64 h60
  text "OTHER +/-" at 12430.46,4102.13 h60
  text "DRILLING:" at 11329.46,3963.64 h60
  text "REFERENCE:" at 11404.23,3846.64 h60
  text "X" at 12052.46,3846.64 h60
  text "AS SHOWN" at 12239.46,3846.64 h60
  text "X" at 12953.46,3846.64 h60
  text "NC_DRILL FILES" at 13090.46,3846.64 h60
  text "PTH COPPER THICKNESS:" at 11404.23,3688.64 h60
  text "X" at 12534.46,3688.64 h60
  text "20-30 um" at 12671.46,3688.64 h60
  text "OTHER" at 13388.46,3688.64 h60
  text "BOARD FINISH:" at 11329.46,3529.64 h60
  text "SILKSCREEN:" at 11484.68,3411.64 h60
  text "X" at 12433.46,3411.64 h60
  text "TOP" at 12559.46,3411.64 h60
  text "X" at 12943.46,3411.64 h60
  text "BOTTOM" at 13070.46,3411.64 h60
  text "SILKSCREEN COLOR:" at 11484.68,3244.64 h60
  text "X" at 12432.42,3244.64 h60
  text "WHITE" at 12559.46,3244.64 h60
  text "OTHER" at 13070.46,3244.64 h60
  text "X" at 12563.42,3085.44 h60
  text "GREEN" at 12690.46,3085.44 h60
  text "OTHER" at 13308.46,3085.44 h60
  text "SOLDER RESIST COLOR:" at 11484.68,3074.64 h60
  text "X" at 12563.42,2915.44 h60
  text "MATTE" at 12690.46,2915.44 h60
  text "SEMI-GLOSS" at 13308,2914.8 h60
  text "IMMERSION GOLD (ENIG)" at 12390.46,2726.92 h60
  text "ENEPIG" at 13728,2723.64 h60
  text "SURFACE FINISH:" at 11329.46,2722.64 h60
  text "X" at 12203.51,2722.64 h60
  text "IMM. TIN/SILVER OR EQUIV" at 11659,2565.64 h60
  text "OTHER" at 13090.46,2565.64 h60
  text "ARRAY/PANEL:" at 11329.46,2386.64 h60
  text "CUT AND TRIM PER M1 BOARD OUTLINE" at 12390.46,2382.35 h60
  text "N.C. ROUTE" at 12390.46,2230.64 h60
  text "X" at 13069.46,2230.64 h60
  text "V. SCORE" at 13256.46,2230.64 h60
  text "CERTIFICATION:" at 11329.46,2093.64 h60
  text "MATERIALS AND WORKMANSHIP FOR ALL PCBS" at 12054.46,2093.64 h60
  text "TO MEET OR EXCEED THE REQUIREMENTS OF:" at 12054.46,1995.64 h60
  text "X" at 11680.96,1859.13 h60
  text "ANSI IPC-A-600F CLASS ->" at 11819.96,1859.13 h60
  text "X" at 13459.02,1859.13 h60
  text "2" at 13577.96,1859.14 h60
  text "1" at 13262.96,1857.64 h60
  text "3" at 13931.96,1857.64 h60
  text "X" at 12495.02,1699.64 h60
  text "RoHS" at 12631.96,1699.64 h60
  text "OTHER" at 13276.36,1699.64 h60
  text "PER ORDER" at 13673.42,1699.64 h60
  text "ALL BOARDS MUST MEET OR EXCEED UL94-V0 REQUIREMENTS." at 11357,1534 h60
  text "PCB MUST BEAR THE UL94V-0 UL REGISTERED MATERIAL ID NUMBER" at 11357,1414 h60
  text "ADDITIONAL REQUIREMENTS:" at 11329.46,1240.64 h60
  text "MICROSECTION:" at 11404.23,1125.64 h60
  text "YES" at 12309.96,1125.64 h60
  text "REQUIRED" at 13171.46,969.49 h60
  text "BARE BOARD ELEC. TEST:" at 11404.23,966.64 h60
  text "NONE" at 12709.96,966.64 h60
  text "X" at 13044.46,966.64 h60
  text "PER ORDER" at 13763.46,966.64 h60
  text ".Layer_Name" at 577,-858.49 h60
M11 Gerber Information:
  lines w10: -292,-930.17 6308,-930.17 ; -292,-726.83 6310,-726.83 ; -292,-523.5 -292,-1133.5 3713,-1133.5 6310,-1133.5 6310,-523.5 -291.5,-523.5 -291.5,-1133.5 1284,-1133.5 ; 2173,-1133.5 2173,-523.5 ; 3440,-726.83 3440,-523.5 ; 4280,-726.83 4280,-523.5 ; 4902,-1140 4902,-937.17
  text "ALL ARTWORK VIEWED FROM TOP SIDE" at -228.5,-655.67 h60
  text "BOARD #:" at 2248,-655.67 h60
  text ".PRJ_Number" at 2793.5,-655.67 h60
  text "REV:" at 3638,-655.67 h60
  text ".PCB_Rev" at 3929.5,-655.67 h60
  text "SVN REV:" at 4476,-655.67 h60
  text ".VersionControl_RevNumber" at 4982,-655.67 h60
  text "LAYER NAME =" at -228.5,-858.49 h60
  text "TID #:" at 2248,-859 h60
  text ".TID" at 2793.5,-859 h60
  text "PLOT NAME =" at -228.5,-1064.34 h60
  text ".plot_File_Name" at 577,-1064.34 h60
  text "GENERATED    :" at 2250,-1064.34 h60
  text ".Print_Date" at 3119.5,-1064.34 h60
  text ".Print_Time" at 3848.5,-1064.34 h60
  text "TEXAS INSTRUMENTS" at 5113,-1064.34 h60
M12 Stackup:
  drawing of 191 lines, arcs and shapes, not listed
  text "Layer" at 9790.34,7830 h60
  text "Name" at 10200.26,7830 h60
  text "Material" at 11130,7830 h60
  text "Thickness" at 11989.77,7830 h60
  text "Constant" at 12639.6,7830 h60
  text "Board Layer Stack" at 13209.46,7830 h60
  text "1" at 9790.34,7710 h60
  text "Top Overlay" at 10200.26,7710 h60
  text "2" at 9790.34,7590 h60
  text "Top Solder" at 10200.26,7590 h60
  text "Solder Resist" at 11130,7590 h60
  text "0.40mil" at 11989.77,7590 h60
  text "3.5" at 12639.6,7590 h60
  text "3" at 9790.34,7470 h60
  text "Top Layer" at 10200.26,7470 h60
  text "Copper" at 11130,7470 h60
  text "1.40mil" at 11989.77,7470 h60
  text "4" at 9790.34,7350 h60
  text "Dielectric1" at 10200.26,7350 h60
  text "FR-4" at 11130,7350 h60
  text "59.20mil" at 11989.77,7350 h60
  text "4.8" at 12639.6,7350 h60
  text "5" at 9790.34,7230 h60
  text "Bottom Layer" at 10200.26,7230 h60
  text "Copper" at 11130,7230 h60
  text "1.40mil" at 11989.77,7230 h60
  text "6" at 9790.34,7110 h60
  text "Bottom Solder" at 10200.26,7110 h60
  text "Solder Resist" at 11130,7110 h60
  text "0.40mil" at 11989.77,7110 h60
  text "3.5" at 12639.6,7110 h60
  text "7" at 9790.34,6990 h60
  text "Bottom Overlay" at 10200.26,6990 h60
  text ".Layer_Name" at 577,-858.49 h60
M13 Component Bodies Top:
  text ".Layer_Name" at 577,-858.49 h60
M14 Component Bodies Bottom:
  text ".Layer_Name" at 577,-858.49 h60
M15 Courtyards Top:
  text ".Layer_Name" at 577,-858.49 h60
M16 Courtyards Bottom:
  text ".Layer_Name" at 577,-858.49 h60
Drill Drawing:
  lines w10: 5336.09,2990.02 5391.34,2990.02 5391.34,3045.27 5336.09,3045.27 5336.09,2990.02 ; 5336.09,3169.59 5391.34,3169.59 5363.72,3114.34 5336.09,3169.59 ; 5336.09,3252.47 5349.9,3252.47 5363.72,3238.66 5377.53,3252.47 5391.34,3252.47 5377.53,3266.28 5391.34,3280.1 5377.53,3280.1 5363.72,3293.91 5349.9,3280.1 5336.09,3280.1 5349.9,3266.28 5336.09,3252.47
  lines w12: 5286,2952.72 8517.49,2952.72 ; 5286,3325.68 8517.49,3325.68 ; 5623.86,2828.4 5623.86,3450 ; 5955.86,2828.4 5955.86,3450 ; 6592.43,2828.4 6592.43,3450 ; 6851.57,2828.4 6851.57,3450 ; 7226.72,2828.4 7226.72,3450 ; 7951.05,2828.4 7951.05,3450 ; 5286,2828.4 8517.49,2828.4 8517.49,3450 5286,3450 5286,2828.4
  text "Symbol" at 5360.59,3362.98 h72
  text "Quantity" at 5661.16,3362.98 h72
  text "Finished Hole Size" at 5993.16,3362.98 h72
  text "Plated" at 6629.72,3362.98 h72
  text "Hole Type" at 6888.86,3362.98 h72
  text "Drill Layer Pair" at 7264.02,3362.98 h72
  text "Hole Tolerance" at 7988.35,3362.98 h72
  text "19" at 5661.16,3238.66 h60
  text "16.00mil (0.406mm)" at 5993.16,3238.66 h60
  text "PTH" at 6629.72,3238.66 h60
  text "Round" at 6888.86,3238.66 h60
  text "Top Layer - Bottom Layer" at 7264.02,3238.66 h60
  text "46" at 5661.16,3114.34 h60
  text "40.00mil (1.016mm)" at 5993.16,3114.34 h60
  text "PTH" at 6629.72,3114.34 h60
  text "Round" at 6888.86,3114.34 h60
  text "Top Layer - Bottom Layer" at 7264.02,3114.34 h60
  text "40" at 5661.16,2990.02 h60
  text "40.94mil (1.040mm)" at 5993.16,2990.02 h60
  text "PTH" at 6629.72,2990.02 h60
  text "Round" at 6888.86,2990.02 h60
  text "Top Layer - Bottom Layer" at 7264.02,2990.02 h60
  text "105 Total" at 5661.16,2865.7 h60
  text ".Layer_Name" at 577,-858.49 h60
M17 Embedded Cavity:
  text ".Layer_Name" at 577,-858.49 h60
M18 Embedded Assembly:
  text ".Layer_Name" at 577,-858.49 h60
M19 Embedded Keepout:
  text ".Layer_Name" at 577,-858.49 h60

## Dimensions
0,-400 to 1000,-400 on M2 Board Dimensions
0,0 to 0,3450 on M2 Board Dimensions
0,0 to 1710,0 on M2 Board Dimensions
